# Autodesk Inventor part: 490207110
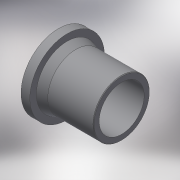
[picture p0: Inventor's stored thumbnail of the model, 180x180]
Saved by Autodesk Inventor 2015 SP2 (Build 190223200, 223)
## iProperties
Created: 2017-07
Part Number: 490207110
Material: Generic
Description: Stub Flange 110
Document SubType Name: Modeling
Designer: Кирилл
Mass: 769.939 g
Surface Area: 1296.06 cm^2
Volume: 769.939 cm^3
Density: 1 g/cm^3
Appearance: Default
Author: Кирилл
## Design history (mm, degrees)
derived "490207.ipt"
feature "Solid1::490207.ipt"
tag "TaggingFeature1"
body "Solid1"
other parameters: "d1" = 125, "d3" = 88, "d4" = 158, "d5" = 18, "d17" = 2.2, "d18" = 2.2, "d19" = 2.2, "d21" = 2.2, "d24" = 2.2, "d25" = 2.2, "d26" = 1.1, "d27" = 0, "d32" = 1.1, "D_" = 158, "D_1" = 125, "a_" = 18
